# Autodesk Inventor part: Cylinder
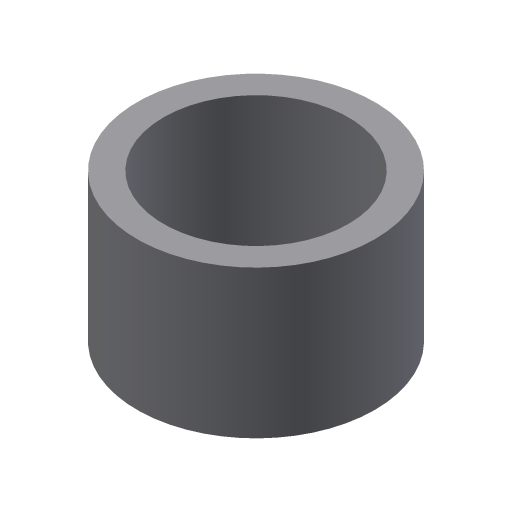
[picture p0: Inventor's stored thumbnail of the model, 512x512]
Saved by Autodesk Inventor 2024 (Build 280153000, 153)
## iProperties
Created: 2010-05
Part Number: Cylinder
Document SubType Name: Modeling
Designer: CADSoft
Density: 1 g/cm^3
Material: Generic
Appearance: Default
Author: CADSoft
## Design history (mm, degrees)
sketch "Sketch1"
  geometry: C1 r 87.5 at (0, 0); C2 r 112.5 at (0, 0); 1 further point
  constraints: 2 centre point, 2 coincident
  dimensions: "d0" = 175 diameter of C1; "d1" = 225 diameter of C2
extrude "Extrusion1" new body sketch "Sketch1" distance "d2" = 140; taper "d3" = 0 deg
body "Solid1"
